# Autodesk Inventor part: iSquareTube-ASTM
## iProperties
Author: Administrator
Shininess: 60.0
PropertySet Name: _Private Model Information
Created: 2000-10
Part Number: iSquareTube-ASTM
Material: Steel, Mild
Document SubType Name: Modeling
Designer: Administrator
Description: 3/8 X 3/8 X 20ga
Control State: 0
Master: False
Checked Out: False
PropertySet Name: Design Tracking Control
Density: 7.86
Volumn: 166.3745698776031
Area: 720.5164130652312
PropertySet Name: Model Information
